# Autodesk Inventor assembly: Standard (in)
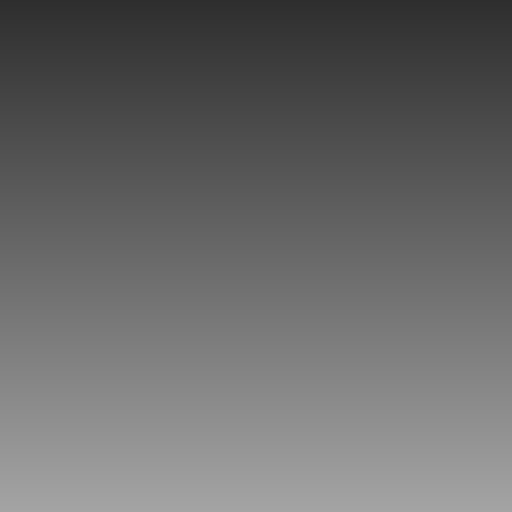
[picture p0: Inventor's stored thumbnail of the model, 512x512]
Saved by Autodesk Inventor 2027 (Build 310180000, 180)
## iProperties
Shininess: 64.0
Length Units: 11272
Angle Units: 11279
Time Units: 11290
Mass Units: 11286
Length Display Precision: 3
Angle Display Precision: 2
Compacted: True
Part Number: Standard (in)
Document SubType Name: Assembly
Created: 2002-07
Designer: invbi
Density: 0.0
Volumn: 0.0
Area: 0.0
PropertySet Name: Model Information
Control State: 0
Master: False
Checked Out: False
Author: invbi
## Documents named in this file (1)
- D:\AUTOBUILD\inventor\Application\App\Templates\en-US\English\Standard (in).iam
